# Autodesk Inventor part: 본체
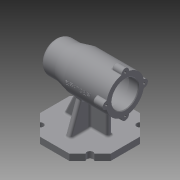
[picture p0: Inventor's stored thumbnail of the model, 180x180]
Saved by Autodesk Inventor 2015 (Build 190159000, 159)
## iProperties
Created: 2019-12
Part Number: 본체
Material: 일반
Document SubType Name: Modeling
Designer: 1010101
Density: 1 g/cm^3
Appearance: 기본값
Author: 1010101
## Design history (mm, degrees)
sketch "스케치1"
  geometry: L1 (23.196, 56)-(56, 23.196); L2 (56, 23.196)-(56, -23.196); L3 (56, -23.196)-(23.196, -56); L4 (23.196, -56)-(-23.196, -56); L5 (-23.196, -56)-(-56, -23.196); L6 (-56, -23.196)-(-56, 23.196); L7 (-56, 23.196)-(-23.196, 56); L8 (-23.196, 56)-(23.196, 56); C1 r 56 at (0, 0); 2 further points
  constraints: 16 end point, 2 coincident, 1 centre point, 1 horizontal, 1 tangent, 17 other
  dimensions: "d0" = 112 diameter of C1
extrude "돌출1" new body sketch "스케치1" distance "d1" = 10; taper "d2" = 0 deg
sketch "스케치2"
  geometry: L1 (23.196, 56)-(-23.196, 56) reference; L2 (-56, 23.196)-(-56, -23.196) reference; L3 (-23.196, -56)-(23.196, -56) reference; L4 (56, -23.196)-(56, 23.196) reference; L5 (-38, -4)-(31, -4); L6 (31, -4)-(31, 4); L7 (31, 4)-(-38, 4); L8 (-38, 4)-(-38, -4); L9 (-4, -36)-(4, -36); L10 (4, -36)-(4, 36); L11 (4, 36)-(-4, 36); L12 (-4, 36)-(-4, -36); 1 further point
  constraints: 16 end point, 4 parallel, 2 horizontal, 2 perpendicular
  dimensions: "d3" = 4 distance from line of point (0, 0) L5; "d4" = 4 distance from line of L10 point (0, 0); "d5" = 8 distance between parallel lines of L10 L12; "d6" = 8 distance between parallel lines of L5 L7; "d7" = 20 distance between parallel lines of L1 L11; "d8" = 20 distance between parallel lines of L3 L9; "d9" = 25 distance between parallel lines of L4 L6; "d10" = 18 distance between parallel lines of L8 L2
extrude "돌출2" join sketch "스케치2" distance "d11" = 70; taper "d12" = 0 deg
feature "면 기울기1" dims angle "d13" = 20 deg
feature "면 기울기2" dims angle "d14" = 20 deg
feature "면 기울기3" dims angle "d15" = 25 deg
sketch "스케치3"
  geometry: L1 (56, 10)-(56, 0) reference; L2 (56, 0)-(-56, 0) reference; L3 (-56, 0)-(-56, 10) reference; L4 (-56, 10)-(-31, 10) reference; L5 (-31, 10)-(-31, 80) reference; L6 (-31, 80)-(5.358, 80) reference; L7 (5.358, 80)-(38, 10) reference; L8 (38, 10)-(56, 10) reference; L9 (56, 80)-(-56, 80); L10 (-56, 80)-(-56, 110); L11 (-56, 110)-(11, 110); L12 (11, 110)-(31, 105); L13 (31, 105)-(56, 105); L14 (56, 105)-(56, 80); 3 further points
  constraints: 12 end point, 3 perpendicular, 2 midpoint, 1 horizontal, 1 parallel, 1 vertical alignment
  dimensions: "d16" = 112 distance of L9.start L9.end; "d17" = 25 distance of L12.end L13.end; "d18" = 45 horizontal distance of L11.end L13.end; "d19" = 30 distance between parallel lines of L9 L11; "d20" = 25 distance of L13.end L9.start; "d21" = 80 distance between parallel lines of L2 L9
revolve "회전1" sketch "스케치3" stored, may be unused: angle "d22" = 90 deg
sketch "스케치4"
  geometry: C1 r 30 at (0, 0) reference; C2 r 21 at (0, 0); 1 further point
  constraints: 1 centre point, 1 coincident
  dimensions: "d23" = 42 diameter of C2
extrude "돌출3" cut sketch "스케치4" distance "d24" = 15; taper "d25" = 0 deg
sketch "스케치5"
  geometry: C1 r 21 at (0, 0) reference; C2 r 24 at (0, 0); 1 further point
  constraints: 1 centre point, 1 coincident
  dimensions: "d26" = 48 diameter of C2
extrude "돌출4" cut sketch "스케치5" distance "d27" = 54; taper "d28" = 0 deg
sketch "스케치6"
  geometry: C1 r 24 at (0, 0) reference; C2 r 21 at (0, 0); 1 further point
  constraints: 1 centre point, 1 coincident
  dimensions: "d29" = 42 diameter of C2
extrude "돌출5" cut sketch "스케치6" distance "d30" = 12; taper "d31" = 0 deg
sketch "스케치7"
  geometry: C1 r 21 at (0, 0) reference; C2 r 17.5 at (0, 0); 1 further point
  constraints: 1 centre point, 1 coincident
  dimensions: "d32" = 35 diameter of C2
extrude "돌출6" cut sketch "스케치7" distance "d33" = 18; taper "d34" = 0 deg
sketch "스케치8"
  geometry: C1 r 17.5 at (0, 0) reference; C2 r 16 at (0, 0); 1 further point
  constraints: 1 centre point, 1 coincident
  dimensions: "d35" = 32 diameter of C2
extrude "돌출7" cut sketch "스케치8" distance "d36" = 4; taper "d37" = 0 deg
sketch "스케치9"
  geometry: C1 r 16 at (0, 0) reference; C2 r 10.5 at (0, 0); 1 further point
  constraints: 1 centre point, 1 coincident
  dimensions: "d38" = 21 diameter of C2
extrude "돌출8" cut sketch "스케치9" distance "d39" = 3; taper "d40" = 0 deg
fillet "모깎기1" dims "d41" = 3
fillet "모깎기2" dims "d42" = 0.3
fillet "모깎기3" dims "d43" = 3
chamfer "모따기1" distance "d44" = 1; stored, may be unused: second distance "d45" = 2, angle "d46" = 45 deg
sketch "스케치10"
  geometry: C1 r 6 at (-30, 0); 3 further points
  constraints: 2 horizontal alignment, 1 centre point, 1 coincident, 1 other
  dimensions: "d47" = 12 diameter of C1
extrude "돌출9" join sketch "스케치10" distance "d48" = 16; taper "d49" = 0 deg
fillet "모깎기4" dims "d50" = 3
fillet "모깎기5" dims "d51" = 1
sketch "스케치11"
  geometry: A1 r 6 centre (0, 0) between (-0.171, 5.998) and (-0.171, -5.998) reference; 1 further point
hole "구멍1" sketch "스케치11" at (0, 0) diameter "d52" = 3.242; stored, may be unused: countersink angle "d56" = 90 deg, drill point angle "d58" = 118 deg; dims "d53" = 8, "d54" = 4, "d55" = 2, "d57" = 11
sketch "스케치12"
  geometry: L1 (23.196, -56)-(56, -23.196) reference; C1 r 5 at (39.598, -39.598); 1 further point
  constraints: 1 centre point, 1 midpoint
  dimensions: "d62" = 10 diameter of C1
extrude "돌출10" cut sketch "스케치12" stored distance "d63" = 16; taper "d64" = 0 deg
fillet "모깎기6" dims "d65" = 3
fillet "모깎기7" dims "d66" = 3
fillet "모깎기8" dims "d67" = 10
fillet "모깎기9" dims "d68" = 3
fillet "모깎기10" dims "d69" = 3
node "작업 평면1"
sketch "스케치13"
  geometry: L1 (33.5, 29.226)-(33.5, 6.771) reference; L2 (0.696, -80)-(-45.696, -80) reference; 2 further points
  constraints: 1 other
  dimensions: "d70" = 45 distance from line of point (-11.5, 0) L1; "d71" = 80 distance from line of L2 point (-11.5, 0)
feature "엠보싱1" sketch "스케치13" dims "d0" = 112, "d72" = 0.5, "d73" = 0
node "솔리드1"
pattern_circular "원형 패턴1" dims "d60" = 360 deg
mirror "대칭1"
mirror "대칭2"
node "절단 모서리 투영1"
